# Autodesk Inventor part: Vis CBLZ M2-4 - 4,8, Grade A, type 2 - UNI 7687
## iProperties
Created: 2002-05
Part Number: Vis CBLZ M2-4 - 4,8, Grade A, type 2 - UNI 7687
Material: Par défaut
Catalog Web Link: www.traceparts.com
Description: Vis CBLZ M2-4 - 4,8, Grade A, type 2 - UNI 7687
Document SubType Name: Modélisation
Designer: Flavien MARTY
Control State: 0
Master: False
Checked Out: False
Shininess: 20.0
Length Units: 11269
Angle Units: 11279
Time Units: 11290
Mass Units: 11283
Length Display Precision: 3
Angle Display Precision: 2
Compacted: True
Density: 0.0
Volumn: 0.0
Area: 0.0
PropertySet Name: Model Information
Author: Flavien MARTY
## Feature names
1. Base1
